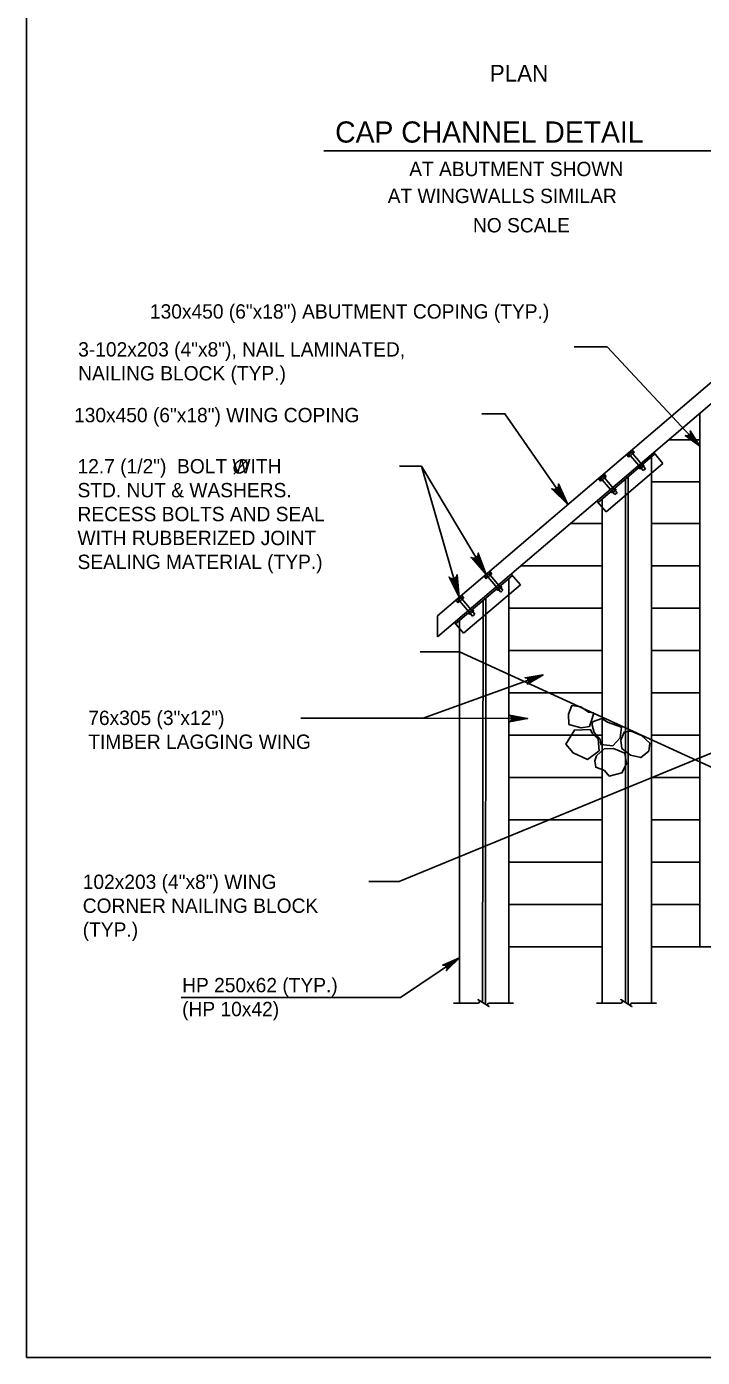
# Model space of a CAD drawing. Extents: x 635440 to 640306, y 296653 to 298484.
# Drawn here: x 639316.5 to 639457.9, y 297856.5 to 298134.8 of the extents above; entities that cross this region are included whole.
import ezdxf

# ---------------------------------------------------------------- set-up
doc = ezdxf.new("R2010")
doc.units = 0
for name, color, linetype in [('2', 7, 'Continuous'), ('3', 7, 'Continuous'), ('4', 7, 'Continuous'), ('5', 7, 'Continuous'), ('8', 7, 'Continuous')]:
    doc.layers.add(name, color=color, linetype=linetype)

# ---------------------------------------------------------------- blocks, each defined once
blk = doc.blocks.new('ROCK')
at = {"layer": '4'}
for points in [[(2.36725, 1.088), (2.2065, 0.82625), (2.378625, 0.506625), (2.66975, 0.3095), (3.128875, 0.403375), (3.48475, 0.6775), (3.4915, 1.123375), (3.25625, 1.36725), (2.783625, 1.308375)], [(1.10175, -0.02725), (1.4015, -0.159125), (1.78825, -0.148875), (1.980875, -0.266), (2.343375, 0.09475), (2.27875, 0.5505), (1.969375, 0.883), (1.4225, 0.553625), (1.152875, 0.479), (1.0105, 0.082)], [(0.74675, 0.359875), (0.882, 0.16), (1.072875, -0.144), (0.892, -0.457375), (0.448125, -0.758625), (0.1, -0.49325), (-0.095, -0.146375), (0.202875, 0.1025), (0.579125, 0.219875)], [(2.231375, -0.71725), (2.2025, -0.266375), (2.45475, 0.037125), (2.9085, 0.28875), (3.2995, 0.047625), (3.46875, -0.344), (3.231625, -0.855), (2.92, -0.860375), (2.5765, -1.054625), (2.340375, -0.904375)], [(1.2085, -0.192875), (0.778375, -0.737625), (1.008375, -1.391375), (1.48725, -1.396875), (2.09825, -1.106625), (2.133375, -0.486375), (1.723125, -0.203375), (1.37425, -0.239875)]]:
    blk.add_lwpolyline(points, close=True, dxfattribs=at)

msp = doc.modelspace()

# ---------------------------------------------------------------- linework, layer by layer
at = {"layer": '2'}
for p, q in [((639316.46, 297856.46), (639316.46, 298420.46)), ((640102.46, 297856.46), (639316.46, 297856.46))]:
    msp.add_line(p, q, dxfattribs=at)
at = {"layer": '3'}
for p, q in [((639463.17, 298063.37), (639402.45, 298011.61)), ((639463.17, 298058.94), (639402.45, 298007.18)), ((639457.33, 298053.97), (639457.33, 297981)), ((639443.63, 298045.78), (639443.16, 298046.32)), ((639450.75, 298048.36), (639457.33, 298048.36)), ((639437.69, 298033.33), (639449.58, 298043.47)), ((639442.44, 298044.76), (639441.97, 298045.3)), ((639442.61, 298044.9), (639442.41, 298045.15)), ((639442.44, 298045.3), (639443.08, 298045.85)), ((639443.63, 298045.78), (639442.44, 298044.76)), ((639442.61, 298045.32), (639442.81, 298045.08)), ((639445.45, 298041.96), (639442.8, 298045.06)), ((639443.03, 298045.68), (639443.23, 298045.44)), ((639443.45, 298045.62), (639443.25, 298045.86)), ((639445.92, 298042.36), (639443.27, 298045.46)), ((639445.42, 298043.32), (639445.62, 298043.08)), ((639447.66, 298045.72), (639449.58, 298043.47)), ((639437.74, 298040.75), (639436.55, 298039.74)), ((639436.56, 298040.29), (639437.19, 298040.83)), ((639437.14, 298040.66), (639437.35, 298040.42)), ((639437.74, 298040.75), (639437.28, 298041.3)), ((639437.57, 298040.6), (639437.36, 298040.84)), ((639444.58, 298042.6), (639444.79, 298042.36)), ((639444.99, 298042.54), (639444.78, 298042.78)), ((639444.95, 298042.37), (639445.58, 298042.92)), ((639445.41, 298042.9), (639445.2, 298043.13)), ((639445.92, 298042.36), (639445.45, 298041.96)), ((639447.22, 298041.45), (639447.22, 297985.04)), ((639436.55, 298039.74), (639436.08, 298040.28)), ((639436.73, 298039.89), (639436.52, 298040.13)), ((639436.73, 298040.3), (639436.93, 298040.06)), ((639439.56, 298036.93), (639436.91, 298040.05)), ((639440.03, 298037.34), (639437.38, 298040.45)), ((639439.09, 298037.51), (639438.89, 298037.75)), ((639439.06, 298037.35), (639439.69, 298037.89)), ((639439.52, 298037.87), (639439.31, 298038.11)), ((639439.53, 298038.3), (639439.73, 298038.06)), ((639447.22, 298039.63), (639457.33, 298039.63)), ((639435.77, 298035.58), (639437.69, 298033.33)), ((639438.69, 298037.58), (639438.89, 298037.34)), ((639440.03, 298037.34), (639439.56, 298036.93)), ((639436.88, 298034.28), (639436.88, 297989.78)), ((639430.27, 298030.89), (639436.88, 298030.89)), ((639447.22, 298030.89), (639457.33, 298030.89)), ((639419.88, 298022.03), (639436.88, 298022.03)), ((639447.22, 298022.03), (639457.33, 298022.03)), ((639412.64, 298019.35), (639412.18, 298019.9)), ((639412.82, 298019.5), (639412.61, 298019.75)), ((639413.83, 298020.37), (639412.64, 298019.35)), ((639412.65, 298019.9), (639413.28, 298020.44)), ((639412.82, 298019.91), (639413.02, 298019.68)), ((639415.66, 298016.56), (639413, 298019.66)), ((639413.24, 298020.27), (639413.44, 298020.03)), ((639413.83, 298020.37), (639413.37, 298020.92)), ((639413.66, 298020.22), (639413.45, 298020.46)), ((639416.13, 298016.96), (639413.47, 298020.06)), ((639417.87, 298020.32), (639419.79, 298018.07)), ((639407.95, 298015.35), (639407.48, 298015.9)), ((639407.89, 298007.93), (639419.79, 298018.07)), ((639414.79, 298017.2), (639414.99, 298016.96)), ((639415.19, 298017.13), (639414.99, 298017.37)), ((639415.15, 298016.97), (639415.79, 298017.52)), ((639415.61, 298017.49), (639415.41, 298017.73)), ((639415.63, 298017.92), (639415.83, 298017.68)), ((639416.13, 298016.96), (639415.66, 298016.56)), ((639417.33, 298015.98), (639417.33, 297999.35)), ((639406.75, 298014.33), (639406.29, 298014.88)), ((639406.93, 298014.48), (639406.73, 298014.73)), ((639407.95, 298015.35), (639406.75, 298014.33)), ((639406.76, 298014.88), (639407.4, 298015.42)), ((639406.93, 298014.89), (639407.13, 298014.66)), ((639409.76, 298011.53), (639407.12, 298014.64)), ((639407.35, 298015.25), (639407.55, 298015.02)), ((639407.77, 298015.2), (639407.56, 298015.44)), ((639410.23, 298011.93), (639407.59, 298015.04)), ((639409.72, 298012.47), (639409.52, 298012.71)), ((639409.73, 298012.89), (639409.94, 298012.65)), ((639417.33, 298013.18), (639436.88, 298013.18)), ((639447.22, 298013.18), (639457.33, 298013.18)), ((639402.45, 298011.61), (639402.45, 298007.18)), ((639405.97, 298010.18), (639407.89, 298007.93)), ((639408.9, 298012.18), (639409.1, 298011.94)), ((639409.3, 298012.11), (639409.1, 298012.35)), ((639409.26, 298011.95), (639409.9, 298012.49)), ((639410.23, 298011.93), (639409.76, 298011.53)), ((639407, 298008.98), (639407, 298003.42)), ((639398.81, 298004.08), (639407, 298004.08)), ((639407, 298003.48), (639407, 297930.56)), ((639407.03, 298004.08), (639469.95, 297975.21)), ((639417.33, 298004.32), (639436.88, 298004.32)), ((639447.22, 298004.32), (639457.33, 298004.32)), ((639417.33, 297999.35), (639417.33, 297930.56)), ((639417.33, 297997.48), (639417.33, 297996.53)), ((639417.33, 297995.46), (639425.81, 297995.46)), ((639425.81, 297995.46), (639436.88, 297995.46)), ((639447.22, 297995.46), (639457.33, 297995.46)), ((639436.88, 297989.78), (639436.88, 297930.56)), ((639417.33, 297986.6), (639436.88, 297986.6)), ((639447.22, 297986.6), (639457.33, 297986.6)), ((639447.22, 297985.04), (639447.22, 297930.56)), ((639457.33, 297981), (639457.33, 297942.31)), ((639417.33, 297977.74), (639436.88, 297977.74)), ((639447.22, 297977.74), (639457.33, 297977.74)), ((639417.33, 297968.88), (639436.88, 297968.88)), ((639447.22, 297968.88), (639457.33, 297968.88)), ((639417.33, 297960.02), (639436.88, 297960.02)), ((639447.22, 297960.02), (639457.33, 297960.02)), ((639417.33, 297951.16), (639436.88, 297951.16)), ((639447.22, 297951.16), (639457.33, 297951.16)), ((639417.33, 297942.31), (639436.88, 297942.31)), ((639447.22, 297942.31), (639466.89, 297942.31))]:
    msp.add_line(p, q, dxfattribs=at)
for centre, radius, start, end in [((639442.54, 298045.2), 0.139, 57.9534, 203.0498), ((639443.04, 298045.24), 0.438, 91.5516, 169.4516), ((639443.17, 298045.73), 0.153, 132.3287, 199.2147), ((639443.17, 298045.73), 0.153, 61.7885, 132.3287), ((639437.15, 298040.22), 0.438, 91.4311, 169.3311), ((639437.29, 298040.71), 0.153, 132.2081, 199.0941), ((639437.29, 298040.71), 0.153, 61.668, 132.2081), ((639444.86, 298042.48), 0.139, 238.0219, 23.1183), ((639444.98, 298042.98), 0.438, 271.6201, 349.5201), ((639445.48, 298043.03), 0.153, 241.8571, 308.7431), ((639445.48, 298043.03), 0.153, 308.7431, 19.2832), ((639436.65, 298040.18), 0.139, 57.8329, 202.9293), ((639439.09, 298037.95), 0.438, 271.4996, 349.3996), ((639439.59, 298038.01), 0.153, 241.7366, 308.6225), ((639439.59, 298038.01), 0.153, 308.6225, 19.1627), ((639438.97, 298037.46), 0.139, 237.9014, 22.9978), ((639412.74, 298019.8), 0.139, 57.9534, 203.0498), ((639413.25, 298019.84), 0.438, 91.5516, 169.4516), ((639413.38, 298020.32), 0.153, 132.3287, 199.2147), ((639413.38, 298020.32), 0.153, 61.7885, 132.3287), ((639415.07, 298017.08), 0.139, 238.0219, 23.1183), ((639415.18, 298017.57), 0.438, 271.6201, 349.5201), ((639415.69, 298017.63), 0.153, 241.8571, 308.7431), ((639415.69, 298017.63), 0.153, 308.7431, 19.2832), ((639406.85, 298014.78), 0.139, 57.8329, 202.9293), ((639407.36, 298014.82), 0.438, 91.4311, 169.3311), ((639407.49, 298015.31), 0.153, 132.2081, 199.0941), ((639407.49, 298015.31), 0.153, 61.668, 132.2081), ((639409.17, 298012.06), 0.139, 237.9014, 22.9978), ((639409.29, 298012.55), 0.438, 271.4996, 349.3996), ((639409.79, 298012.6), 0.153, 241.7366, 308.6225), ((639409.79, 298012.6), 0.153, 308.6225, 19.1627)]:
    msp.add_arc(centre, radius, start, end, dxfattribs=at)
at = {"layer": '4'}
for p, q in [((639378.64, 298108.82), (639461.55, 298108.82)), ((639424.51, 297999.21), (639399.4, 297990.17)), ((639421.19, 297990.07), (639399.4, 297990.17)), ((639407, 297940.03), (639394.7, 297931.75)), ((639394.7, 297931.75), (639348.81, 297931.75))]:
    msp.add_line(p, q, dxfattribs=at)
for points in [[(639457.33, 298047.07), (639437.95, 298067.85)], [(639457.33, 298047.07), (639454.28, 298049.32), (639454.62, 298049.24), (639454.9, 298049.3), (639455.11, 298049.44), (639455.27, 298049.64), (639455.35, 298049.92), (639455.3, 298050.27), (639457.33, 298047.07), (639455.35, 298049.92), (639455.27, 298049.64), (639457.33, 298047.07), (639455.11, 298049.44), (639454.9, 298049.3), (639457.33, 298047.07), (639454.62, 298049.24)], [(639424.51, 297999.21), (639421.24, 297997.29), (639421.44, 297997.58), (639421.49, 297997.86), (639421.45, 297998.11), (639421.32, 297998.33), (639421.1, 297998.51), (639420.76, 297998.61), (639424.51, 297999.21), (639421.1, 297998.51), (639421.32, 297998.33), (639424.51, 297999.21), (639421.45, 297998.11), (639421.49, 297997.86), (639424.51, 297999.21), (639421.44, 297997.58)], [(639421.19, 297990.07), (639417.46, 297989.39), (639417.75, 297989.59), (639417.9, 297989.84), (639417.94, 297990.09), (639417.9, 297990.34), (639417.75, 297990.59), (639417.46, 297990.79), (639421.19, 297990.07), (639417.75, 297990.59), (639417.9, 297990.34), (639421.19, 297990.07), (639417.94, 297990.09), (639417.9, 297989.84), (639421.19, 297990.07), (639417.75, 297989.59)], [(639463.94, 297984.59), (639394.38, 297956.03)], [(639407, 297940.03), (639404.29, 297937.37), (639404.42, 297937.69), (639404.4, 297937.98), (639404.3, 297938.21), (639404.12, 297938.4), (639403.86, 297938.52), (639403.51, 297938.53), (639407, 297940.03), (639403.86, 297938.52), (639404.12, 297938.4), (639407, 297940.03), (639404.3, 297938.21), (639404.4, 297937.98), (639407, 297940.03), (639404.42, 297937.69)]]:
    msp.add_lwpolyline(points, dxfattribs=at)
for points in [[(639457.33, 298047.07), (639455.5, 298049.39), (639455.14, 298049.06)], [(639421.56, 297998.68), (639421.89, 297997.75), (639424.51, 297999.21)], [(639418.34, 297990.58), (639418.34, 297989.6), (639421.29, 297990.07)], [(639404.38, 297938.84), (639404.91, 297938.05), (639407, 297940.03)]]:
    msp.add_lwpolyline(points, close=True, dxfattribs=at)
at = {"layer": '5'}
for p, q in [((639437.95, 298067.85), (639431.01, 298067.85)), ((639359.82, 298041.2), (639362.62, 298044.26)), ((639399.4, 297990.17), (639373.85, 297990.17)), ((639394.38, 297956.03), (639388.06, 297956.03))]:
    msp.add_line(p, q, dxfattribs=at)
for points in [[(639429.7, 298034.84), (639416.54, 298053.84), (639411.68, 298053.84)], [(639412.58, 298020.24), (639399.07, 298042.91), (639394.45, 298042.91)], [(639406.97, 298015.46), (639399.07, 298042.91)], [(639429.7, 298034.84), (639426.33, 298038.17), (639426.54, 298038.1), (639426.74, 298038.02), (639426.92, 298038.03), (639427.1, 298038.05), (639427.25, 298038.11), (639427.39, 298038.18), (639427.5, 298038.29), (639427.62, 298038.4), (639427.69, 298038.57), (639427.77, 298038.73), (639427.77, 298038.95), (639427.77, 298039.17), (639429.7, 298034.84), (639427.77, 298038.95), (639427.77, 298038.73), (639429.7, 298034.84), (639427.69, 298038.57), (639427.62, 298038.4), (639429.7, 298034.84), (639427.5, 298038.29), (639427.39, 298038.18), (639429.7, 298034.84), (639427.25, 298038.11), (639427.1, 298038.05), (639429.7, 298034.84), (639426.92, 298038.03), (639426.74, 298038.02), (639429.7, 298034.84), (639426.54, 298038.1)], [(639412.58, 298020.24), (639409.44, 298023.8), (639409.64, 298023.71), (639409.84, 298023.62), (639410.02, 298023.62), (639410.2, 298023.62), (639410.35, 298023.67), (639410.5, 298023.73), (639410.62, 298023.83), (639410.74, 298023.94), (639410.83, 298024.1), (639410.91, 298024.26), (639410.93, 298024.47), (639410.94, 298024.69), (639412.58, 298020.24), (639410.93, 298024.47), (639410.91, 298024.26), (639412.58, 298020.24), (639410.83, 298024.1), (639410.74, 298023.94), (639412.58, 298020.24), (639410.62, 298023.83), (639410.5, 298023.73), (639412.58, 298020.24), (639410.35, 298023.67), (639410.2, 298023.62), (639412.58, 298020.24), (639410.02, 298023.62), (639409.84, 298023.62), (639412.58, 298020.24), (639409.64, 298023.71)], [(639406.97, 298015.46), (639404.84, 298019.7), (639405.01, 298019.56), (639405.18, 298019.42), (639405.36, 298019.37), (639405.53, 298019.33), (639405.69, 298019.35), (639405.85, 298019.36), (639405.99, 298019.43), (639406.13, 298019.5), (639406.26, 298019.63), (639406.38, 298019.77), (639406.45, 298019.97), (639406.52, 298020.18), (639406.97, 298015.46), (639406.45, 298019.97), (639406.38, 298019.77), (639406.97, 298015.46), (639406.26, 298019.63), (639406.13, 298019.5), (639406.97, 298015.46), (639405.99, 298019.43), (639405.85, 298019.36), (639406.97, 298015.46), (639405.69, 298019.35), (639405.53, 298019.33), (639406.97, 298015.46), (639405.36, 298019.37), (639405.18, 298019.42), (639406.97, 298015.46), (639405.01, 298019.56)]]:
    msp.add_lwpolyline(points, dxfattribs=at)
msp.add_spline([(639362.33, 298043.96), (639362.11, 298044.13), (639361.89, 298044.19), (639361.61, 298044.21), (639361.46, 298044.21), (639361.19, 298044.15), (639360.94, 298044.04), (639360.77, 298043.94), (639360.44, 298043.68), (639360.18, 298043.34), (639360.02, 298043.02), (639359.93, 298042.73), (639359.91, 298042.46), (639359.93, 298042.23), (639360.05, 298041.9), (639360.16, 298041.73), (639360.41, 298041.55), (639360.77, 298041.46), (639361.18, 298041.48), (639361.7, 298041.71), (639362.08, 298042.04), (639362.37, 298042.44), (639362.56, 298042.85), (639362.62, 298043.31), (639362.54, 298043.61), (639362.34, 298043.96)], degree=3, dxfattribs=at)
at = {"layer": '8'}
for p, q in [((639436.01, 298035.3), (639447.91, 298045.44)), ((639447.22, 298044.85), (639447.22, 298041.45)), ((639442.34, 298040.7), (639442.34, 297930.31)), ((639441.75, 298040.19), (639441.75, 297930.68)), ((639436.88, 298035.85), (639436.88, 298034.28)), ((639406.22, 298009.9), (639418.11, 298020.03)), ((639417.33, 298019.37), (639417.33, 298015.97)), ((639411.96, 298014.79), (639411.87, 297930.68)), ((639412.55, 298015.29), (639412.46, 297930.31)), ((639407, 298010.56), (639407, 298008.98)), ((639410.9, 297930.56), (639405.8, 297930.56)), ((639418.33, 297930.56), (639413.23, 297930.56)), ((639440.79, 297930.56), (639435.69, 297930.56)), ((639448.22, 297930.56), (639443.12, 297930.56))]:
    msp.add_line(p, q, dxfattribs=at)
for points in [[(639413.06, 297929.92), (639413.21, 297929.83), (639410.9, 297931.29), (639411.05, 297931.19)], [(639442.95, 297929.92), (639443.09, 297929.83), (639440.78, 297931.29), (639440.94, 297931.19)]]:
    msp.add_lwpolyline(points, dxfattribs=at)
for centre, start, end in [((639410.87, 297930.9), 275.3286, 57.8672), ((639413.23, 297930.22), 90, 240), ((639440.75, 297930.9), 275.3286, 57.8672), ((639443.12, 297930.22), 90, 240)]:
    msp.add_arc(centre, 0.341, start, end, dxfattribs=at)

# ---------------------------------------------------------------- block references
at = {"layer": '4', "xscale": 4.921475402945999, "yscale": 4.921475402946, "rotation": -50.14527635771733}
msp.add_blockref('ROCK', (639431.39, 297992.95), dxfattribs=at)

# ---------------------------------------------------------------- texts
at = {"layer": '4'}
for s, height, p in [('PLAN', 3.5, (639413.37, 298123.33)), ('CAP CHANNEL DETAIL', 4.4294, (639381.02, 298110.57)), ('AT ABUTMENT SHOWN', 3.0001, (639396.51, 298103.55)), ('AT WINGWALLS SIMILAR', 3.0001, (639392.01, 298097.92)), ('NO SCALE', 3, (639409.85, 298091.79)), ('HP 250x62 (TYP.)', 3.0001, (639349, 297932.83)), ('(HP 10x42)', 3, (639349, 297927.83))]:
    msp.add_text(s, height=height, dxfattribs=at).set_placement(p)
at = {"layer": '5'}
for s, height, p in [('130x450 (6"x18") ABUTMENT COPING (TYP.)', 3.0001, (639342.26, 298073.75)), ('3-102x203 (4"x8"), NAIL LAMINATED,', 3.0001, (639327.25, 298065.82)), ('NAILING BLOCK (TYP.)', 3.0001, (639327.25, 298060.82)), ('130x450 (6"x18") WING COPING', 3.0001, (639326.38, 298052.07)), ('12.7 (1/2")  BOLT WITH', 3.0001, (639327.11, 298041.37)), ('STD. NUT & WASHERS.', 3.0001, (639327.11, 298036.37)), ('RECESS BOLTS AND SEAL', 3.0001, (639327.11, 298031.37)), ('WITH RUBBERIZED JOINT', 3.0001, (639327.11, 298026.37)), ('SEALING MATERIAL (TYP.)', 3.0001, (639327.11, 298021.37)), ('76x305 (3"x12")', 3.0001, (639329.36, 297988.74)), ('TIMBER LAGGING WING', 3.0001, (639329.36, 297983.74)), ('102x203 (4"x8") WING', 3.0001, (639328.2, 297954.44)), ('CORNER NAILING BLOCK', 3.0001, (639328.2, 297949.44)), ('(TYP.)', 3, (639328.2, 297944.44))]:
    msp.add_text(s, height=height, dxfattribs=at).set_placement(p)

doc.saveas('drawing.dxf')
